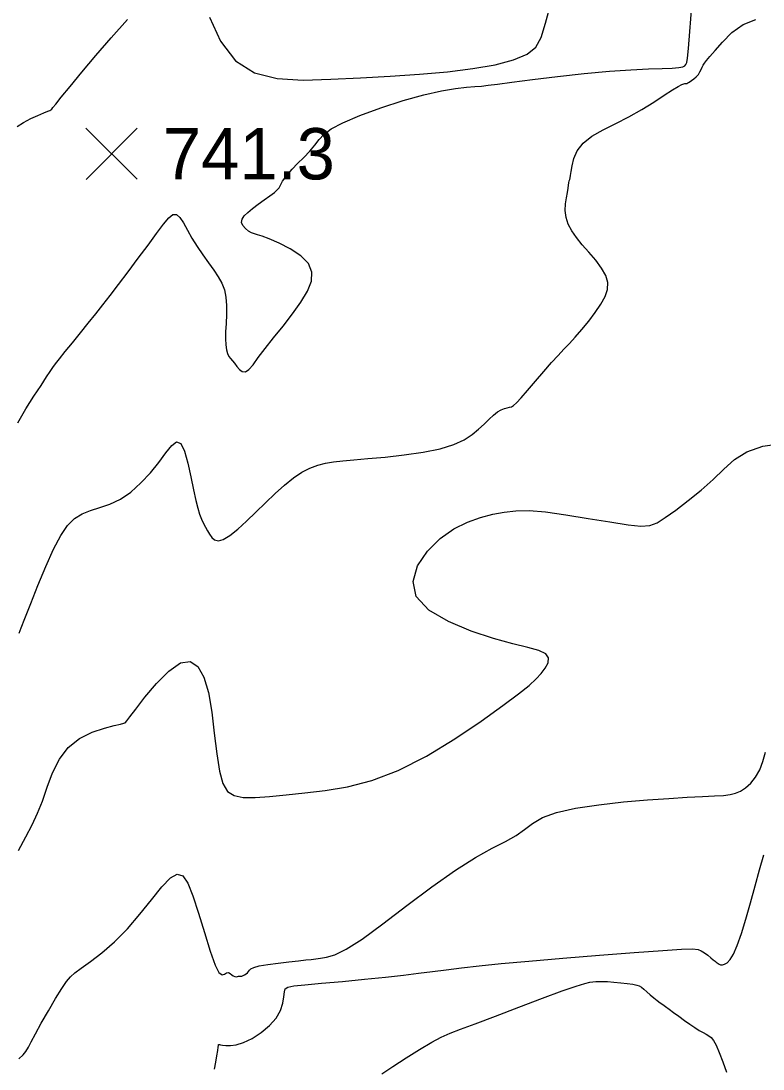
# Model space of a CAD drawing. Extents: x 2566142 to 2571431, y 418755 to 421584.
# Drawn here: x 2568693.7 to 2568910.3, y 420754.1 to 421060.3 of the extents above; entities that cross this region are included whole.
import ezdxf

# ---------------------------------------------------------------- set-up
doc = ezdxf.new("R2010")
doc.units = 0
for name, color, linetype in [('Contour_ADS_Major', 7, 'Continuous'), ('Contour_ADS_Minor', 7, 'Continuous'), ('Contour_ADS_Spot_Elevation', 7, 'Continuous')]:
    doc.layers.add(name, color=color, linetype=linetype)

# ---------------------------------------------------------------- blocks, each defined once
blk = doc.blocks.new('S750')
at = {"layer": 'Contour_ADS_Spot_Elevation'}
for p, q in [((-0.5, 0.498), (0.5, -0.498)), ((-0.498, -0.5), (0.498, 0.5))]:
    blk.add_line(p, q, dxfattribs=at)

msp = doc.modelspace()

# ---------------------------------------------------------------- linework, layer by layer
at = {"layer": 'Contour_ADS_Major'}
for points in [[(2568745.1, 420994.4), (2568746.76, 420992), (2568748.42, 420989.7), (2568749.95, 420987.55), (2568751.26, 420985.6), (2568752.29, 420983.72), (2568753.05, 420981.78), (2568753.51, 420979.63), (2568753.68, 420977.19), (2568753.66, 420974.58), (2568753.53, 420971.97), (2568753.42, 420969.54), (2568753.41, 420967.44), (2568753.5, 420965.69), (2568753.7, 420964.27), (2568754, 420963.17), (2568754.39, 420962.34), (2568754.86, 420961.69), (2568755.41, 420961.06), (2568756.03, 420960.32), (2568756.71, 420959.4), (2568757.46, 420958.5), (2568758.29, 420957.89), (2568759.19, 420957.81), (2568760.2, 420958.5), (2568761.41, 420959.91), (2568762.95, 420961.98), (2568764.94, 420964.63), (2568767.42, 420967.76), (2568770.18, 420971.2), (2568772.94, 420974.74), (2568775.41, 420978.18), (2568777.32, 420981.36), (2568778.46, 420984.28), (2568778.63, 420986.96), (2568777.61, 420989.44), (2568775.35, 420991.74), (2568772.29, 420993.77), (2568769.03, 420995.45), (2568766.16, 420996.69), (2568764.11, 420997.43), (2568762.76, 420997.83), (2568761.82, 420998.09), (2568760.99, 420998.41), (2568760.07, 420998.95), (2568759.17, 420999.68), (2568758.45, 421000.53), (2568758.09, 421001.46), (2568758.22, 421002.39), (2568758.83, 421003.36), (2568759.86, 421004.4), (2568761.25, 421005.53), (2568762.91, 421006.77), (2568764.68, 421008.03), (2568766.33, 421009.22), (2568767.66, 421010.24), (2568768.51, 421011), (2568769.01, 421011.6), (2568769.32, 421012.14), (2568769.62, 421012.74), (2568770.05, 421013.48), (2568770.69, 421014.42), (2568771.61, 421015.57), (2568772.85, 421016.98), (2568774.44, 421018.64), (2568776.22, 421020.46), (2568777.97, 421022.31), (2568779.5, 421024.06), (2568780.74, 421025.65), (2568782.13, 421027.17), (2568784.23, 421028.77), (2568787.61, 421030.59), (2568792.63, 421032.71), (2568798.76, 421034.96), (2568805.25, 421037.06), (2568811.34, 421038.78), (2568816.44, 421039.93), (2568820.53, 421040.6), (2568823.74, 421040.95), (2568826.2, 421041.14), (2568828.12, 421041.31), (2568830.11, 421041.54), (2568832.85, 421041.9), (2568837.01, 421042.45), (2568843.04, 421043.21), (2568850.35, 421044.08), (2568858.11, 421044.93), (2568865.48, 421045.63), (2568871.78, 421046.07), (2568876.9, 421046.31), (2568880.9, 421046.44), (2568883.82, 421046.55), (2568885.76, 421046.71), (2568886.91, 421046.93), (2568887.52, 421047.23), (2568887.83, 421047.6), (2568888.05, 421048.16), (2568888.27, 421049.49), (2568888.56, 421052.27), (2568888.97, 421057.21), (2568889.53, 421064.66)], [(2568692.69, 420942.9), (2568695.09, 420946.98), (2568697.43, 420950.69), (2568699.51, 420953.87), (2568701.14, 420956.31), (2568702.22, 420957.95), (2568702.99, 420959.1), (2568703.77, 420960.18), (2568704.89, 420961.62), (2568706.56, 420963.71), (2568708.67, 420966.32), (2568710.99, 420969.19), (2568713.31, 420972.05), (2568715.47, 420974.72), (2568717.56, 420977.35), (2568719.74, 420980.15), (2568722.18, 420983.34), (2568724.96, 420987.04), (2568727.91, 420990.99), (2568730.76, 420994.85), (2568733.27, 420998.27), (2568735.26, 421000.95), (2568736.79, 421002.79), (2568738.01, 421003.76), (2568739.05, 421003.8), (2568740.06, 421002.92), (2568741.09, 421001.31), (2568742.24, 420999.21), (2568743.56, 420996.84), (2568745.1, 420994.4)], [(2568799.04, 420752.72), (2568802.25, 420754.87), (2568806.1, 420757.37), (2568810.06, 420759.85), (2568813.6, 420761.96), (2568816.39, 420763.44), (2568818.94, 420764.57), (2568821.99, 420765.73), (2568826.25, 420767.31), (2568832.18, 420769.55), (2568839.07, 420772.18), (2568845.91, 420774.79), (2568851.73, 420776.96), (2568855.76, 420778.37), (2568858.27, 420779.15), (2568859.74, 420779.5), (2568860.67, 420779.62), (2568861.51, 420779.69), (2568862.42, 420779.74), (2568863.53, 420779.74), (2568864.97, 420779.68), (2568866.78, 420779.55), (2568868.78, 420779.36), (2568870.71, 420779.14), (2568872.33, 420778.91), (2568873.45, 420778.68), (2568874.22, 420778.41), (2568874.83, 420778.02), (2568875.5, 420777.47), (2568876.38, 420776.71), (2568877.41, 420775.83), (2568878.47, 420774.93), (2568879.45, 420774.14), (2568880.28, 420773.52), (2568881.04, 420772.98), (2568881.87, 420772.4), (2568882.9, 420771.66), (2568884.22, 420770.68), (2568885.76, 420769.53), (2568887.38, 420768.33), (2568888.97, 420767.2), (2568890.42, 420766.23), (2568891.71, 420765.43), (2568892.82, 420764.78), (2568893.77, 420764.28), (2568894.55, 420763.86), (2568895.24, 420763.35), (2568895.92, 420762.49), (2568896.67, 420761.08), (2568897.57, 420758.95), (2568898.58, 420756.25), (2568899.65, 420753.21)]]:
    msp.add_lwpolyline(points, dxfattribs=at)
at = {"layer": 'Contour_ADS_Minor'}
for points in [[(2568748.69, 421061.45), (2568751.93, 421054.44), (2568756.28, 421048.69), (2568761.85, 421045.14), (2568768.51, 421043.47), (2568776.02, 421043.07), (2568784.18, 421043.33), (2568792.76, 421043.73), (2568801.47, 421044.2), (2568810.04, 421044.78), (2568818.19, 421045.51), (2568825.63, 421046.42), (2568832.14, 421047.55), (2568837.49, 421048.92), (2568841.47, 421050.58), (2568844, 421052.63), (2568845.58, 421055.5), (2568846.85, 421059.69), (2568848.46, 421065.7)], [(2568708.03, 421041.22), (2568711.47, 421045.36), (2568715.54, 421050.2), (2568720.04, 421055.43), (2568724.76, 421060.79)], [(2568836.29, 420947.46), (2568836.85, 420947.62), (2568837.47, 420947.99), (2568838.35, 420948.78), (2568839.68, 420950.22), (2568841.59, 420952.41), (2568843.89, 420955.09), (2568846.31, 420957.91), (2568848.58, 420960.51), (2568850.51, 420962.63), (2568852.2, 420964.41), (2568853.81, 420966.12), (2568855.51, 420967.99), (2568857.43, 420970.2), (2568859.43, 420972.65), (2568861.35, 420975.18), (2568863, 420977.62), (2568864.22, 420979.83), (2568864.92, 420981.88), (2568865.03, 420983.89), (2568864.47, 420985.95), (2568863.22, 420988.15), (2568861.48, 420990.44), (2568859.52, 420992.73), (2568857.57, 420994.95), (2568855.87, 420997.05), (2568854.49, 420999.04), (2568853.47, 421000.99), (2568852.84, 421002.94), (2568852.61, 421004.93), (2568852.69, 421006.88), (2568852.93, 421008.68), (2568853.21, 421010.23), (2568853.43, 421011.45), (2568853.57, 421012.38), (2568853.68, 421013.08), (2568853.77, 421013.59), (2568853.88, 421013.99), (2568854, 421014.46), (2568854.15, 421015.18), (2568854.33, 421016.33), (2568854.58, 421018.03), (2568855.1, 421020.13), (2568856.1, 421022.4), (2568857.82, 421024.63), (2568860.39, 421026.64), (2568863.64, 421028.5), (2568867.33, 421030.35), (2568871.18, 421032.31), (2568874.95, 421034.46), (2568878.45, 421036.63), (2568881.51, 421038.61), (2568883.92, 421040.19), (2568885.58, 421041.2), (2568886.61, 421041.74), (2568887.2, 421041.96), (2568887.54, 421042.02), (2568887.79, 421042.04), (2568888.05, 421042.1), (2568888.37, 421042.24), (2568888.82, 421042.49), (2568889.43, 421042.89), (2568890.14, 421043.43), (2568890.84, 421044.05), (2568891.46, 421044.73), (2568891.92, 421045.44), (2568892.25, 421046.14), (2568892.53, 421046.81), (2568892.83, 421047.43), (2568893.23, 421048.02), (2568893.85, 421048.76), (2568894.84, 421049.9), (2568896.35, 421051.67), (2568898.5, 421054.17), (2568901.24, 421056.92), (2568904.51, 421059.31), (2568908.27, 421060.72)], [(2568692.5, 421029.53), (2568694.38, 421030.69), (2568696.52, 421031.79), (2568698.61, 421032.74), (2568700.33, 421033.48), (2568701.46, 421033.96), (2568702.08, 421034.21), (2568702.36, 421034.32), (2568702.45, 421034.35), (2568702.49, 421034.38), (2568702.52, 421034.41), (2568702.53, 421034.44), (2568702.55, 421034.48), (2568702.62, 421034.58), (2568702.95, 421035), (2568703.8, 421036.05), (2568705.44, 421038.05), (2568708.03, 421041.22)], [(2568693.15, 420881.49), (2568693.74, 420882.98), (2568694.83, 420885.77), (2568696.51, 420890.09), (2568698.62, 420895.41), (2568700.92, 420900.97), (2568703.2, 420906.03), (2568705.29, 420909.99), (2568707.27, 420912.91), (2568709.28, 420914.97), (2568711.48, 420916.38), (2568713.97, 420917.35), (2568716.71, 420918.17), (2568719.64, 420919.15), (2568722.67, 420920.59), (2568725.71, 420922.71), (2568728.68, 420925.36), (2568731.44, 420928.31), (2568733.89, 420931.32), (2568735.95, 420934.11), (2568737.66, 420936.27), (2568739.09, 420937.35), (2568740.33, 420936.9), (2568741.44, 420934.66), (2568742.42, 420931.16), (2568743.3, 420927.13), (2568744.05, 420923.3), (2568744.71, 420920.26), (2568745.29, 420917.96), (2568745.82, 420916.19), (2568746.35, 420914.77), (2568746.91, 420913.53), (2568747.49, 420912.4), (2568748.09, 420911.35), (2568748.72, 420910.36), (2568749.4, 420909.43), (2568750.21, 420908.72), (2568751.29, 420908.46), (2568752.74, 420908.84), (2568754.66, 420910.01), (2568756.95, 420911.85), (2568759.53, 420914.18), (2568762.26, 420916.81), (2568765.06, 420919.55), (2568767.86, 420922.25), (2568770.6, 420924.74), (2568773.23, 420926.87), (2568775.69, 420928.51), (2568778.04, 420929.71), (2568780.33, 420930.56), (2568782.6, 420931.14), (2568784.95, 420931.55), (2568787.62, 420931.86), (2568790.85, 420932.15), (2568794.93, 420932.48), (2568799.98, 420932.93), (2568805.58, 420933.53), (2568811.14, 420934.31), (2568816.11, 420935.31), (2568820.05, 420936.55), (2568823.07, 420937.96), (2568825.39, 420939.48), (2568827.27, 420941.03), (2568828.91, 420942.55), (2568830.37, 420943.95), (2568831.67, 420945.17), (2568832.84, 420946.12), (2568833.88, 420946.75), (2568834.81, 420947.13), (2568835.62, 420947.34), (2568836.29, 420947.46)], [(2568725.43, 420857.03), (2568727.16, 420859.27), (2568729.87, 420862.74), (2568733.24, 420866.73), (2568736.84, 420870.37), (2568740.23, 420872.77), (2568743.06, 420873.23), (2568745.31, 420871.78), (2568747.06, 420868.66), (2568748.37, 420864.09), (2568749.34, 420858.4), (2568750.1, 420852.21), (2568750.8, 420846.22), (2568751.58, 420841.16), (2568752.6, 420837.55), (2568754, 420835.26), (2568755.94, 420834.01), (2568758.58, 420833.49), (2568762.02, 420833.44), (2568766.21, 420833.72), (2568771.08, 420834.21), (2568776.53, 420834.83), (2568782.49, 420835.52), (2568788.99, 420836.6), (2568796.08, 420838.41), (2568803.79, 420841.35), (2568812.07, 420845.58), (2568820.35, 420850.61), (2568828, 420855.74), (2568834.35, 420860.29), (2568838.93, 420863.73), (2568842.01, 420866.22), (2568844.05, 420868.11), (2568845.52, 420869.7), (2568846.75, 420871.28), (2568847.58, 420872.81), (2568847.73, 420874.22), (2568846.92, 420875.42), (2568844.9, 420876.38), (2568841.66, 420877.3), (2568837.24, 420878.4), (2568831.66, 420879.92), (2568825.12, 420882.07), (2568818.49, 420884.85), (2568812.8, 420888.22), (2568809.1, 420892.16), (2568808.13, 420896.56), (2568809.45, 420901.12), (2568812.35, 420905.43), (2568816.09, 420909.12), (2568820.07, 420911.91), (2568824.04, 420913.88), (2568827.88, 420915.24), (2568831.48, 420916.19), (2568834.79, 420916.86), (2568838.16, 420917.25), (2568842.02, 420917.28), (2568846.82, 420916.89), (2568852.78, 420916.07), (2568859.32, 420915.01), (2568865.63, 420913.95), (2568870.93, 420913.13), (2568874.66, 420912.76), (2568877.26, 420912.95), (2568879.4, 420913.75), (2568881.77, 420915.25), (2568884.86, 420917.45), (2568888.48, 420920.19), (2568892.25, 420923.24), (2568895.79, 420926.39), (2568898.9, 420929.43), (2568901.97, 420932.17), (2568905.58, 420934.46), (2568910.29, 420936.11), (2568916.42, 420937.02)], [(2568692.97, 420817.99), (2568695.08, 420821.97), (2568696.89, 420825.47), (2568698.48, 420828.84), (2568699.92, 420832.42), (2568701.33, 420836.43), (2568702.9, 420840.63), (2568704.86, 420844.64), (2568707.46, 420848.09), (2568710.79, 420850.68), (2568714.48, 420852.5), (2568718.01, 420853.7), (2568720.88, 420854.46), (2568722.71, 420854.92), (2568723.67, 420855.16), (2568724.03, 420855.27), (2568724.11, 420855.31), (2568724.18, 420855.4), (2568724.53, 420855.86), (2568725.43, 420857.03)], [(2568905.23, 420836.33), (2568906.74, 420837.69), (2568908.17, 420839.41), (2568909.39, 420841.52), (2568910.33, 420844), (2568911.07, 420846.68)], [(2568693.04, 420757.11), (2568694.27, 420758.27), (2568695.11, 420759.3), (2568695.82, 420760.48), (2568696.66, 420762.09), (2568697.87, 420764.4), (2568699.6, 420767.56), (2568701.66, 420771.18), (2568703.75, 420774.73), (2568705.56, 420777.7), (2568706.92, 420779.72), (2568708.08, 420781.08), (2568709.41, 420782.21), (2568711.28, 420783.57), (2568713.95, 420785.52), (2568717.27, 420788.11), (2568720.95, 420791.31), (2568724.74, 420795.1), (2568728.39, 420799.35), (2568731.77, 420803.61), (2568734.77, 420807.33), (2568737.3, 420809.97), (2568739.31, 420811.06), (2568740.93, 420810.55), (2568742.38, 420808.44), (2568743.85, 420804.75), (2568745.48, 420799.67), (2568747.2, 420793.98), (2568748.86, 420788.6), (2568750.32, 420784.49), (2568751.48, 420782.31), (2568752.38, 420781.65), (2568753.08, 420781.86), (2568753.67, 420782.25), (2568754.21, 420782.31), (2568754.72, 420782.06), (2568755.19, 420781.68), (2568755.64, 420781.33), (2568756.07, 420781.15), (2568756.48, 420781.11), (2568756.86, 420781.16), (2568757.21, 420781.22), (2568757.52, 420781.25), (2568757.83, 420781.26), (2568758.15, 420781.31), (2568758.51, 420781.43), (2568758.94, 420781.64), (2568759.39, 420781.93), (2568759.81, 420782.27), (2568760.14, 420782.65), (2568760.4, 420783.03), (2568760.81, 420783.43), (2568761.65, 420783.83), (2568763.23, 420784.24), (2568765.7, 420784.67), (2568768.73, 420785.08), (2568771.87, 420785.46), (2568774.66, 420785.76), (2568776.79, 420785.99), (2568778.39, 420786.16), (2568779.75, 420786.31), (2568781.16, 420786.48), (2568782.89, 420786.77), (2568785.27, 420787.53), (2568788.61, 420789.16), (2568793.25, 420792.08), (2568799.34, 420796.51), (2568806.37, 420801.86), (2568813.65, 420807.36), (2568820.5, 420812.25), (2568826.36, 420815.94), (2568831.2, 420818.61), (2568835.12, 420820.64), (2568838.22, 420822.38), (2568840.67, 420824.14), (2568843.04, 420825.9), (2568845.93, 420827.58), (2568849.99, 420829.08), (2568855.62, 420830.33), (2568862.38, 420831.35), (2568869.6, 420832.15), (2568876.61, 420832.76), (2568882.86, 420833.21), (2568888.22, 420833.53), (2568892.66, 420833.75), (2568896.19, 420833.92), (2568898.82, 420834.07), (2568900.77, 420834.3), (2568902.32, 420834.69), (2568903.74, 420835.34), (2568905.23, 420836.33)], [(2568750.12, 420754.05), (2568750.53, 420756.11), (2568750.87, 420758.02), (2568751.11, 420759.54), (2568751.26, 420760.51), (2568751.33, 420761.02), (2568751.36, 420761.22), (2568751.38, 420761.27), (2568751.43, 420761.29), (2568751.58, 420761.29), (2568751.92, 420761.25), (2568752.52, 420761.15), (2568753.47, 420761.01), (2568754.79, 420760.97), (2568756.5, 420761.19), (2568758.64, 420761.86), (2568761.15, 420763.1), (2568763.79, 420764.8), (2568766.25, 420766.84), (2568768.22, 420769.04), (2568769.47, 420771.27), (2568770.14, 420773.39), (2568770.44, 420775.23), (2568770.58, 420776.65), (2568770.82, 420777.56), (2568771.58, 420778.09), (2568773.33, 420778.42), (2568776.53, 420778.73), (2568781.45, 420779.18), (2568787.52, 420779.74), (2568794, 420780.36), (2568800.12, 420780.99), (2568805.31, 420781.56), (2568809.75, 420782.1), (2568813.81, 420782.62), (2568817.85, 420783.14), (2568822.25, 420783.68), (2568827.43, 420784.26), (2568833.85, 420784.92), (2568841.94, 420785.67), (2568851.85, 420786.51), (2568862.55, 420787.38), (2568872.73, 420788.17), (2568881.05, 420788.79), (2568886.56, 420789.14), (2568889.73, 420789.24), (2568891.37, 420789.08), (2568892.32, 420788.69), (2568893.24, 420788.09), (2568894.19, 420787.38), (2568895.08, 420786.66), (2568895.82, 420786.04), (2568896.33, 420785.61), (2568896.68, 420785.32), (2568896.95, 420785.12), (2568897.22, 420784.94), (2568897.55, 420784.75), (2568897.97, 420784.6), (2568898.49, 420784.56), (2568899.12, 420784.72), (2568899.86, 420785.17), (2568900.71, 420786.1), (2568901.69, 420787.71), (2568902.79, 420790.2), (2568904.01, 420793.69), (2568905.32, 420797.96), (2568906.67, 420802.71), (2568908.03, 420807.61), (2568909.35, 420812.37), (2568910.58, 420816.74)]]:
    msp.add_lwpolyline(points, dxfattribs=at)

# ---------------------------------------------------------------- block references
at = {"layer": 'Contour_ADS_Spot_Elevation', "xscale": 15, "yscale": 15}
msp.add_blockref('S750', (2568720.12, 421021.53), dxfattribs=at)

# ---------------------------------------------------------------- texts
at = {"layer": 'Contour_ADS_Spot_Elevation'}
msp.add_text('741.3', height=15, dxfattribs=at).set_placement((2568735.12, 421014.03))

doc.saveas('drawing.dxf')
